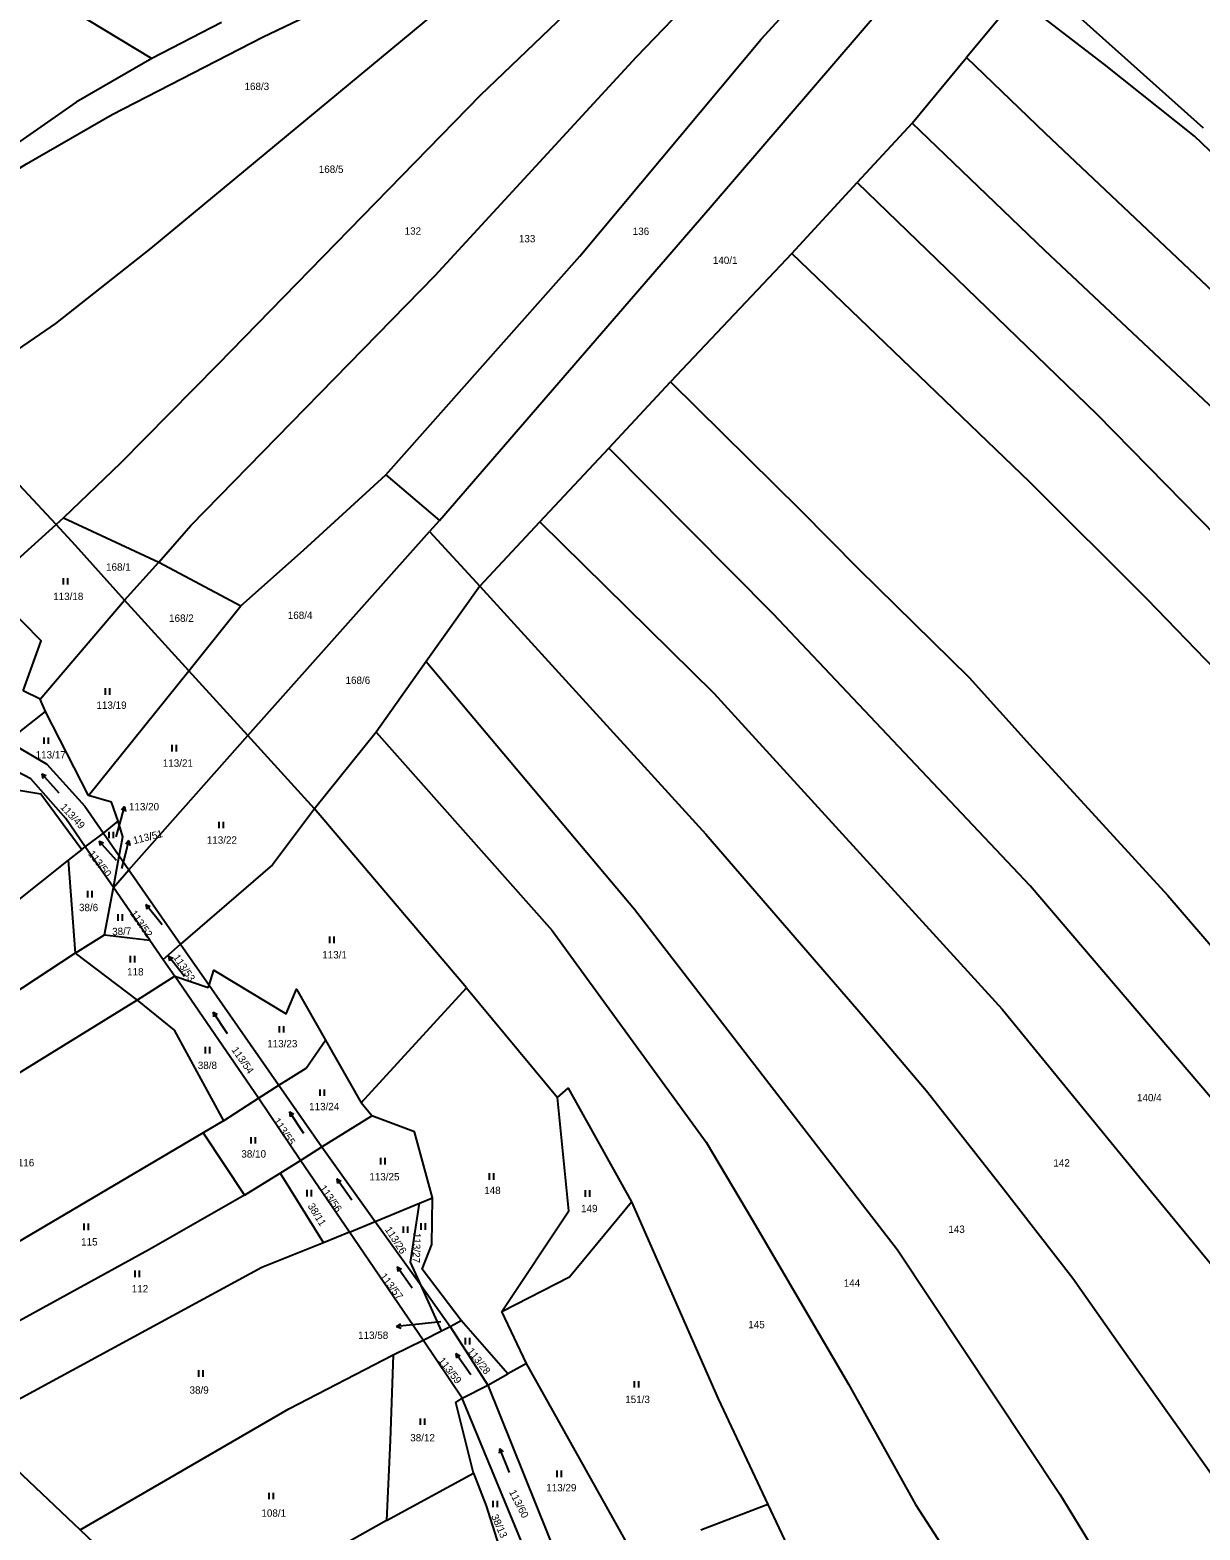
# Model space of a CAD drawing. Extents: x -7476540 to -746055, y -11317203 to -1129777.
# Drawn here: x -747546.5 to -747276.5, y -1131141.4 to -1130795.4 of the extents above; entities that cross this region are included whole.
import ezdxf

# ---------------------------------------------------------------- set-up
doc = ezdxf.new("R2010")
doc.units = 0
for name, color, linetype in [('Hranice parcel', 7, 'Continuous'), ('Parcelní čísla', 7, 'Continuous'), ('Pop  PČ popisy', 7, 'Continuous'), ('Značky kultur', 7, 'Continuous')]:
    doc.layers.add(name, color=color, linetype=linetype)

msp = doc.modelspace()

# ---------------------------------------------------------------- linework, layer by layer
at = {"layer": 'Hranice parcel'}
for p, q in [((-747318.79, -1130787.77), (-747330.4, -1130801.79)), ((-747275.7, -1130818.09), (-747307.66, -1130789.55)), ((-747502.34, -1130793.69), (-747518.4, -1130801.96)), ((-747342.93, -1130816.92), (-747330.4, -1130801.79)), ((-747342.93, -1130816.92), (-747355.62, -1130830.63)), ((-747370.72, -1130846.96), (-747355.62, -1130830.63)), ((-747370.72, -1130846.96), (-747398.68, -1130876.61)), ((-747412.97, -1130891.88), (-747398.68, -1130876.61)), ((-747540.5, -1130909.52), (-747566.95, -1130881.22)), ((-747428.85, -1130908.85), (-747412.97, -1130891.88)), ((-747464.43, -1130898), (-747452.04, -1130908.53)), ((-747538.78, -1130907.97), (-747540.5, -1130909.52)), ((-747538.78, -1130907.97), (-747516.82, -1130918.2)), ((-747556.37, -1130923.79), (-747540.5, -1130909.52)), ((-747496.26, -1130958.17), (-747454.36, -1130911.13)), ((-747452.04, -1130908.53), (-747454.36, -1130911.13)), ((-747454.36, -1130911.13), (-747442.73, -1130923.69)), ((-747442.73, -1130923.69), (-747428.85, -1130908.85)), ((-747524.7, -1130926.96), (-747516.82, -1130918.2)), ((-747516.82, -1130918.2), (-747497.88, -1130928.23)), ((-747442.73, -1130923.69), (-747455.08, -1130941.09)), ((-747544.17, -1130949.82), (-747524.7, -1130926.96)), ((-747509.89, -1130943.21), (-747524.7, -1130926.96)), ((-747509.89, -1130943.21), (-747497.88, -1130928.23)), ((-747455.08, -1130941.09), (-747466.65, -1130957.41)), ((-747533.01, -1130972.03), (-747509.89, -1130943.21)), ((-747496.26, -1130958.17), (-747509.89, -1130943.21)), ((-747544.17, -1130949.82), (-747548.12, -1130947.84)), ((-747542.97, -1130952.61), (-747544.17, -1130949.82)), ((-747551.66, -1130959.44), (-747542.97, -1130952.61)), ((-747533.01, -1130972.03), (-747542.97, -1130952.61)), ((-747523.68, -1130989.16), (-747496.26, -1130958.17)), ((-747480.85, -1130975.08), (-747496.26, -1130958.17)), ((-747466.65, -1130957.41), (-747480.85, -1130975.08)), ((-747445.77, -1131016.39), (-747480.85, -1130975.08)), ((-747533.76, -1130983.87), (-747529.57, -1130980.67)), ((-747529.57, -1130980.67), (-747526.17, -1130977.92)), ((-747529.57, -1130980.67), (-747525.94, -1130985.9)), ((-747534.58, -1130984.5), (-747537.72, -1130986.92)), ((-747534.58, -1130984.5), (-747533.76, -1130983.87)), ((-747527.29, -1130993.25), (-747533.76, -1130983.87)), ((-747537.72, -1130986.92), (-747536.11, -1131008.38)), ((-747527.29, -1130993.25), (-747525.94, -1130985.9)), ((-747525.94, -1130985.9), (-747523.68, -1130989.16)), ((-747527.29, -1130993.25), (-747523.68, -1130989.16)), ((-747523.68, -1130989.16), (-747511.77, -1131006.31)), ((-747529.3, -1131004.16), (-747527.29, -1130993.25)), ((-747518.9, -1131005.41), (-747527.29, -1130993.25)), ((-747536.11, -1131008.38), (-747529.3, -1131004.16)), ((-747529.3, -1131004.16), (-747518.9, -1131005.41)), ((-747536.11, -1131008.38), (-747521.83, -1131019.25)), ((-747518.9, -1131005.41), (-747515.79, -1131009.83)), ((-747515.79, -1131009.83), (-747511.77, -1131006.31)), ((-747511.77, -1131006.31), (-747505.21, -1131015.73)), ((-747515.79, -1131009.83), (-747513.08, -1131013.69)), ((-747513.08, -1131013.69), (-747521.83, -1131019.25)), ((-747493.76, -1131041.86), (-747513.08, -1131013.69)), ((-747505.21, -1131015.73), (-747489.11, -1131038.86)), ((-747470.12, -1131042.87), (-747445.77, -1131016.39)), ((-747445.77, -1131016.39), (-747424.82, -1131041.7)), ((-747478.31, -1131028.41), (-747470.12, -1131042.87)), ((-747493.76, -1131041.86), (-747489.11, -1131038.86)), ((-747489.11, -1131038.86), (-747479.21, -1131053.09)), ((-747501.87, -1131047.09), (-747493.76, -1131041.86)), ((-747484.08, -1131056.18), (-747493.76, -1131041.86)), ((-747467.67, -1131045.88), (-747470.12, -1131042.87)), ((-747479.21, -1131053.09), (-747467.67, -1131045.88)), ((-747501.87, -1131047.09), (-747506.57, -1131049.83)), ((-747506.57, -1131049.83), (-747497.04, -1131064.23)), ((-747484.08, -1131056.18), (-747479.21, -1131053.09)), ((-747479.21, -1131053.09), (-747466.89, -1131070.28)), ((-747488.78, -1131059.1), (-747484.08, -1131056.18)), ((-747472.77, -1131072.73), (-747484.08, -1131056.18)), ((-747497.04, -1131064.23), (-747488.78, -1131059.1)), ((-747488.78, -1131059.1), (-747478.83, -1131075.18)), ((-747466.89, -1131070.28), (-747456.65, -1131066.03)), ((-747456.65, -1131066.03), (-747453.62, -1131064.84)), ((-747472.77, -1131072.73), (-747466.89, -1131070.28)), ((-747466.89, -1131070.28), (-747456.29, -1131085.07)), ((-747472.77, -1131072.73), (-747478.83, -1131075.18)), ((-747455.83, -1131097.63), (-747472.77, -1131072.73)), ((-747456.29, -1131085.07), (-747449.55, -1131094.47)), ((-747451.56, -1131095.48), (-747456.29, -1131085.07)), ((-747431.95, -1131103.02), (-747437.65, -1131091.07)), ((-747451.56, -1131095.48), (-747449.55, -1131094.47)), ((-747449.55, -1131094.47), (-747447.06, -1131093.1)), ((-747449.55, -1131094.47), (-747440.84, -1131108.03)), ((-747436.27, -1131105.41), (-747447.06, -1131093.1)), ((-747462.74, -1131101.03), (-747455.83, -1131097.63)), ((-747455.83, -1131097.63), (-747451.56, -1131095.48)), ((-747446.81, -1131111.05), (-747455.83, -1131097.63)), ((-747440.84, -1131108.03), (-747436.27, -1131105.41)), ((-747431.95, -1131103.02), (-747436.27, -1131105.41)), ((-747408.38, -1131145.07), (-747431.95, -1131103.02)), ((-747446.81, -1131111.05), (-747440.84, -1131108.03)), ((-747440.84, -1131108.03), (-747424.22, -1131149.41)), ((-747430.18, -1131151.04), (-747446.81, -1131111.05)), ((-747551.23, -1131125.94), (-747534.94, -1131141.41)), ((-747464.26, -1131139.24), (-747444.14, -1131128.36)), ((-747376.22, -1131135.6), (-747391.74, -1131141.48)), ((-747518.15, -1131157.34), (-747534.94, -1131141.41))]:
    msp.add_line(p, q, dxfattribs=at)
for points in [[(-747650.43, -1130722.5), (-747624.13, -1130740.43), (-747611.24, -1130748.86), (-747568.75, -1130772.25), (-747551.99, -1130781.63), (-747518.4, -1130801.96)], [(-747592.89, -1130855.02), (-747567.07, -1130838.41), (-747547.35, -1130826.32), (-747527.53, -1130814.88), (-747492.89, -1130797.06), (-747472.69, -1130787.42), (-747441.69, -1130763.28), (-747417.46, -1130747.1), (-747393.87, -1130731.74)], [(-747566.95, -1130881.22), (-747540.53, -1130863.15), (-747518.65, -1130845.8), (-747451.1, -1130789.94), (-747421.34, -1130761.04), (-747390.31, -1130735.18)], [(-747375.64, -1130746.37), (-747442.58, -1130810.47), (-747503.21, -1130872.55), (-747525.65, -1130895.32), (-747538.78, -1130907.97)], [(-747516.82, -1130918.2), (-747509.43, -1130909.76), (-747453.02, -1130852.06), (-747406.54, -1130801.59), (-747362.47, -1130755.89)], [(-747464.43, -1130898), (-747419.65, -1130847.56), (-747377.79, -1130797.57), (-747349.46, -1130766.63)], [(-747452.04, -1130908.53), (-747389.53, -1130836.33), (-747337.16, -1130775.31)], [(-747003.4, -1131127.9), (-747038.28, -1131074.83), (-747088.46, -1131014.6), (-747116.47, -1130986.19), (-747124.97, -1130976.78), (-747183.56, -1130913.69), (-747214.38, -1130881.51), (-747246.16, -1130850.11), (-747277.78, -1130819.92), (-747298.57, -1130803.35), (-747318.79, -1130787.77)], [(-747518.4, -1130801.96), (-747535.86, -1130812.1), (-747550.62, -1130822.39), (-747567.45, -1130834.27)], [(-747330.4, -1130801.79), (-747312.28, -1130819.2), (-747236.13, -1130891.14), (-747221.8, -1130905.72), (-747180.22, -1130949.79), (-747146.85, -1130983.32), (-747109.33, -1131021.53), (-747071.58, -1131064.23), (-747049.91, -1131090.84), (-747024.34, -1131132)], [(-747047.94, -1131136.47), (-747061.48, -1131111.93), (-747077.88, -1131090.42), (-747092.86, -1131072.81), (-747117.23, -1131044.76), (-747147.18, -1131012.65), (-747177.53, -1130980.93), (-747224.92, -1130930.97), (-747274.38, -1130881.89), (-747312.29, -1130846.28), (-747342.93, -1130816.92)], [(-747355.62, -1130830.63), (-747300.42, -1130884), (-747284.49, -1130900.18), (-747229.45, -1130956.25), (-747195.44, -1130993.87), (-747158.72, -1131032.34), (-747137.46, -1131054.25), (-747087.92, -1131108.9), (-747067.99, -1131140.68)], [(-747092.53, -1131145.47), (-747103.44, -1131128.5), (-747151.55, -1131074.46), (-747210.89, -1131009.26), (-747228.17, -1130990.46), (-747257.09, -1130959.39), (-747288.71, -1130926.72), (-747315.79, -1130899.71), (-747370.72, -1130846.96)], [(-747398.68, -1130876.61), (-747368.77, -1130906.07), (-747355.31, -1130919.74), (-747329.82, -1130944.76), (-747315.8, -1130960.3), (-747283.94, -1130995.04), (-747236.86, -1131049.77), (-747149.88, -1131157.26)], [(-747177.21, -1131162.4), (-747204.46, -1131125.99), (-747254.48, -1131065.07), (-747271.84, -1131044.18), (-747315.73, -1130992.85), (-747375, -1130930.12), (-747412.97, -1130891.88)], [(-747497.88, -1130928.23), (-747483.39, -1130915.42), (-747464.43, -1130898)], [(-747524.7, -1130926.96), (-747536.03, -1130914.31), (-747540.5, -1130909.52)], [(-747428.85, -1130908.85), (-747388.68, -1130948.41), (-747322.17, -1131021.26), (-747287.68, -1131063.4), (-747257.57, -1131100.06), (-747233.11, -1131129.78), (-747216.94, -1131150.33), (-747204.99, -1131167.77)], [(-747548.12, -1130947.84), (-747543.96, -1130936.32), (-747556.37, -1130923.79)], [(-747442.73, -1130923.69), (-747390.58, -1130980.92), (-747354.26, -1131022.92), (-747339.61, -1131040.16), (-747322.4, -1131062.04), (-747305.83, -1131083.32), (-747294.44, -1131099.65), (-747274.04, -1131128.34), (-747243.06, -1131175.98)], [(-747455.08, -1130941.09), (-747407, -1130998.24), (-747346.3, -1131076.82), (-747308.86, -1131133.19), (-747276.68, -1131185.78)], [(-747551.66, -1130959.44), (-747542.61, -1130964.81), (-747533.86, -1130974.48), (-747529.57, -1130980.67)], [(-747466.65, -1130957.41), (-747426.05, -1131003.14), (-747390.52, -1131051.98), (-747379.77, -1131069.99), (-747357.62, -1131107.84), (-747342.16, -1131135.57), (-747326.23, -1131160.19), (-747318.42, -1131169.83), (-747304.55, -1131193.5)], [(-747533.76, -1130983.87), (-747538.28, -1130977.32), (-747546.35, -1130968.19), (-747556.12, -1130963.07)], [(-747562.63, -1130968.51), (-747544.05, -1130971.62), (-747534.58, -1130984.5)], [(-747526.17, -1130977.92), (-747527.69, -1130973.54), (-747533.01, -1130972.03)], [(-747480.85, -1130975.08), (-747490.53, -1130988), (-747511.77, -1131006.31)], [(-747525.94, -1130985.9), (-747525.13, -1130981.52), (-747526.17, -1130977.92)], [(-747537.72, -1130986.92), (-747564.39, -1131008.14), (-747611.03, -1131036.67), (-747627.11, -1131046.39)], [(-747536.11, -1131008.38), (-747587.97, -1131042.46), (-747616.38, -1131059.15)], [(-747513.08, -1131013.69), (-747505.41, -1131016.33), (-747505.21, -1131015.73)], [(-747505.21, -1131015.73), (-747504.08, -1131012.3), (-747487.41, -1131022.36), (-747485.06, -1131016.72), (-747478.31, -1131028.41)], [(-747521.83, -1131019.25), (-747565.86, -1131046.34), (-747605.42, -1131071.52)], [(-747521.83, -1131019.25), (-747513.23, -1131026.12), (-747501.87, -1131047.09)], [(-747489.11, -1131038.86), (-747482.82, -1131034.88), (-747478.31, -1131028.41)], [(-747424.82, -1131041.7), (-747422.32, -1131039.54), (-747407.71, -1131065.71)], [(-747437.65, -1131091.07), (-747422.19, -1131067.82), (-747424.82, -1131041.7)], [(-747453.62, -1131064.84), (-747457.76, -1131049.58), (-747467.67, -1131045.88)], [(-747506.57, -1131049.83), (-747567.11, -1131085.51), (-747578.6, -1131091.89), (-747583.1, -1131094.79)], [(-747497.04, -1131064.23), (-747519.1, -1131076.81), (-747571.91, -1131105.73)], [(-747456.29, -1131085.07), (-747458.74, -1131079.69), (-747456.65, -1131066.03)], [(-747447.06, -1131093.1), (-747456, -1131081.28), (-747453.76, -1131075.58), (-747453.62, -1131064.84)], [(-747437.65, -1131091.07), (-747422, -1131083.03), (-747407.71, -1131065.71)], [(-747407.71, -1131065.71), (-747387.68, -1131111.18), (-747376.22, -1131135.6)], [(-747478.83, -1131075.18), (-747493.05, -1131080.92), (-747560.11, -1131117.26)], [(-747534.94, -1131141.41), (-747486.76, -1131113.5), (-747462.74, -1131101.03)], [(-747462.74, -1131101.03), (-747463.44, -1131120.77), (-747464.26, -1131139.24)], [(-747444.14, -1131128.36), (-747448.25, -1131112.03), (-747446.81, -1131111.05)], [(-747444.14, -1131128.36), (-747441.29, -1131135.89), (-747437.88, -1131146.58), (-747434.26, -1131152.16)], [(-747376.22, -1131135.6), (-747368.67, -1131151.69), (-747335.3, -1131202.07)], [(-747464.26, -1131139.24), (-747483.41, -1131150.03), (-747508, -1131163.09)]]:
    msp.add_lwpolyline(points, dxfattribs=at)
at = {"layer": 'Pop  PČ popisy'}
for p, q in [((-747526.65, -1130981.51), (-747525.51, -1130977.47)), ((-747525.51, -1130977.47), (-747524.68, -1130974.58)), ((-747524.68, -1130974.58), (-747525.44, -1130975.41)), ((-747524.68, -1130974.58), (-747524.48, -1130975.69)), ((-747524.43, -1130985.33), (-747523.7, -1130982.42)), ((-747523.7, -1130982.42), (-747524.43, -1130983.27)), ((-747523.7, -1130982.42), (-747523.46, -1130983.51)), ((-747525.3, -1130988.86), (-747524.43, -1130985.33)), ((-747461.92, -1131094.51), (-747460.97, -1131093.91)), ((-747458.93, -1131094.2), (-747461.92, -1131094.51)), ((-747461.92, -1131094.51), (-747460.87, -1131094.91)), ((-747451.68, -1131093.42), (-747458.93, -1131094.2))]:
    msp.add_line(p, q, dxfattribs=at)
at = {"layer": 'Značky kultur'}
for p, q in [((-747538.76, -1130923.37), (-747538.76, -1130921.87)), ((-747537.76, -1130923.37), (-747537.76, -1130921.87)), ((-747529.1, -1130948.78), (-747529.1, -1130947.28)), ((-747528.1, -1130948.78), (-747528.1, -1130947.28)), ((-747543.24, -1130960.1), (-747543.24, -1130958.6)), ((-747542.24, -1130960.1), (-747542.24, -1130958.6)), ((-747513.74, -1130961.83), (-747513.74, -1130960.33)), ((-747512.74, -1130961.83), (-747512.74, -1130960.33)), ((-747539.8, -1130971.47), (-747543.81, -1130967.01)), ((-747543.81, -1130967.01), (-747543.53, -1130968.07)), ((-747543.81, -1130967.01), (-747542.79, -1130967.4)), ((-747528.22, -1130981.85), (-747528.22, -1130980.35)), ((-747527.22, -1130981.85), (-747527.22, -1130980.35)), ((-747502.9, -1130979.58), (-747502.9, -1130978.08)), ((-747501.9, -1130979.58), (-747501.9, -1130978.08)), ((-747526.57, -1130986.97), (-747530.58, -1130982.51)), ((-747530.58, -1130982.51), (-747530.3, -1130983.57)), ((-747530.58, -1130982.51), (-747529.56, -1130982.9)), ((-747533.17, -1130995.51), (-747533.17, -1130994.01)), ((-747532.17, -1130995.51), (-747532.17, -1130994.01)), ((-747516, -1131001.81), (-747519.77, -1130997.15)), ((-747519.77, -1130997.15), (-747519.55, -1130998.23)), ((-747519.77, -1130997.15), (-747518.77, -1130997.59)), ((-747526.2, -1131000.89), (-747526.2, -1130999.39)), ((-747525.2, -1131000.89), (-747525.2, -1130999.39)), ((-747477.3, -1131006.05), (-747477.3, -1131004.55)), ((-747476.3, -1131006.05), (-747476.3, -1131004.55)), ((-747523.33, -1131010.52), (-747523.33, -1131009.02)), ((-747522.33, -1131010.52), (-747522.33, -1131009.02)), ((-747510.87, -1131013.79), (-747514.56, -1131009.07)), ((-747514.56, -1131009.07), (-747514.35, -1131010.15)), ((-747514.56, -1131009.07), (-747513.56, -1131009.53)), ((-747500.93, -1131026.98), (-747504.28, -1131022)), ((-747504.28, -1131022), (-747504.15, -1131023.09)), ((-747504.28, -1131022), (-747503.32, -1131022.53)), ((-747488.94, -1131026.68), (-747488.94, -1131025.18)), ((-747487.94, -1131026.68), (-747487.94, -1131025.18)), ((-747506.04, -1131031.49), (-747506.04, -1131029.99)), ((-747505.04, -1131031.49), (-747505.04, -1131029.99)), ((-747479.54, -1131041.31), (-747479.54, -1131039.81)), ((-747478.54, -1131041.31), (-747478.54, -1131039.81)), ((-747483.3, -1131049.99), (-747486.65, -1131045.01)), ((-747486.65, -1131045.01), (-747486.52, -1131046.1)), ((-747486.65, -1131045.01), (-747485.69, -1131045.54)), ((-747495.49, -1131052.29), (-747495.49, -1131050.79)), ((-747494.49, -1131052.29), (-747494.49, -1131050.79)), ((-747465.54, -1131057.13), (-747465.54, -1131055.63)), ((-747464.54, -1131057.13), (-747464.54, -1131055.63)), ((-747472.25, -1131065.37), (-747475.69, -1131060.45)), ((-747475.69, -1131060.45), (-747475.54, -1131061.54)), ((-747475.69, -1131060.45), (-747474.72, -1131060.97)), ((-747440.46, -1131060.63), (-747440.46, -1131059.13)), ((-747439.46, -1131060.63), (-747439.46, -1131059.13)), ((-747482.54, -1131064.49), (-747482.54, -1131062.99)), ((-747481.54, -1131064.49), (-747481.54, -1131062.99)), ((-747418.34, -1131064.58), (-747418.34, -1131063.08)), ((-747417.34, -1131064.58), (-747417.34, -1131063.08)), ((-747533.99, -1131072.27), (-747533.99, -1131070.77)), ((-747532.99, -1131072.27), (-747532.99, -1131070.77)), ((-747456.23, -1131072.2), (-747456.23, -1131070.7)), ((-747455.23, -1131072.2), (-747455.23, -1131070.7)), ((-747460.34, -1131072.91), (-747460.34, -1131071.41)), ((-747459.34, -1131072.91), (-747459.34, -1131071.41)), ((-747458.35, -1131085.65), (-747461.79, -1131080.73)), ((-747461.79, -1131080.73), (-747461.64, -1131081.82)), ((-747461.79, -1131080.73), (-747460.82, -1131081.25)), ((-747522.27, -1131083.09), (-747522.27, -1131081.59)), ((-747521.27, -1131083.09), (-747521.27, -1131081.59)), ((-747446.04, -1131098.65), (-747446.04, -1131097.15)), ((-747445.04, -1131098.65), (-747445.04, -1131097.15)), ((-747444.81, -1131105.63), (-747448.25, -1131100.71)), ((-747448.25, -1131100.71), (-747448.1, -1131101.8)), ((-747448.25, -1131100.71), (-747447.28, -1131101.23)), ((-747507.6, -1131106.09), (-747507.6, -1131104.59)), ((-747506.6, -1131106.09), (-747506.6, -1131104.59)), ((-747407.04, -1131108.61), (-747407.04, -1131107.11)), ((-747406.04, -1131108.61), (-747406.04, -1131107.11)), ((-747456.41, -1131117.21), (-747456.41, -1131115.71)), ((-747455.41, -1131117.21), (-747455.41, -1131115.71)), ((-747438.13, -1131122.64), (-747438.23, -1131123.73)), ((-747435.89, -1131128.2), (-747438.13, -1131122.64)), ((-747438.13, -1131122.64), (-747437.3, -1131123.36)), ((-747424.88, -1131129.23), (-747424.88, -1131127.73)), ((-747423.88, -1131129.23), (-747423.88, -1131127.73)), ((-747491.32, -1131134.35), (-747491.32, -1131132.85)), ((-747490.32, -1131134.35), (-747490.32, -1131132.85)), ((-747439.63, -1131136.2), (-747439.63, -1131134.7)), ((-747438.63, -1131136.2), (-747438.63, -1131134.7))]:
    msp.add_line(p, q, dxfattribs=at)

# ---------------------------------------------------------------- texts
at = {"layer": 'Parcelní čísla'}
for s, p in [('168/3', (-747497.02, -1130809.28)), ('168/5', (-747479.88, -1130828.38)), ('132', (-747460.07, -1130842.63)), ('136', (-747407.43, -1130842.7)), ('133', (-747433.7, -1130844.4)), ('140/1', (-747388.94, -1130849.39)), ('168/1', (-747528.97, -1130920.14)), ('113/18', (-747541.17, -1130926.92)), ('168/2', (-747514.43, -1130931.95)), ('168/4', (-747487.03, -1130931.28)), ('168/6', (-747473.71, -1130946.27)), ('113/19', (-747531.19, -1130952.02)), ('113/17', (-747545.22, -1130963.46)), ('113/21', (-747515.88, -1130965.38)), ('113/20', (-747523.69, -1130975.43)), ('113/22', (-747505.72, -1130983.13)), ('38/6', (-747535.22, -1130998.69)), ('113/1', (-747479.08, -1131009.6)), ('118', (-747524.11, -1131013.52)), ('113/23', (-747491.78, -1131030.1)), ('38/8', (-747507.8, -1131035.1)), ('113/24', (-747482.11, -1131044.61)), ('140/4', (-747291.06, -1131042.55)), ('116', (-747549.33, -1131057.56)), ('38/10', (-747497.75, -1131055.53)), ('142', (-747310.35, -1131057.61)), ('113/25', (-747468.21, -1131060.8)), ('148', (-747441.7, -1131063.95)), ('149', (-747419.35, -1131068.13)), ('115', (-747534.73, -1131075.82)), ('143', (-747334.59, -1131072.91)), ('144', (-747358.73, -1131085.33)), ('112', (-747523.04, -1131086.64)), ('145', (-747380.76, -1131094.9)), ('113/58', (-747470.81, -1131097.37)), ('38/9', (-747509.71, -1131110.01)), ('151/3', (-747409.16, -1131112.16)), ('38/12', (-747458.77, -1131121)), ('113/29', (-747427.38, -1131132.53)), ('108/1', (-747493.12, -1131138.39))]:
    msp.add_text(s, height=1.7, dxfattribs=at).set_placement(p)
for s, rotation, p in [('113/49', 313, (-747539.66, -1130974.8)), ('113/51', 14, (-747522.5, -1130983.24)), ('113/50', 308, (-747533.21, -1130985.52)), ('113/52', 305, (-747523.52, -1130999.23)), ('38/7', 2, (-747527.53, -1131004.26)), ('113/53', 304, (-747513.58, -1131009.35)), ('113/54', 305, (-747500.1, -1131030.7)), ('113/55', 304, (-747490.46, -1131047.1)), ('113/56', 305, (-747479.79, -1131062.6)), ('38/11', 302, (-747482.52, -1131066.7)), ('113/26', 303, (-747464.71, -1131072.12)), ('113/27', 268, (-747458.02, -1131072.87)), ('113/57', 307, (-747465.84, -1131082.95)), ('113/59', 308, (-747452.4, -1131102.42)), ('113/28', 308, (-747445.72, -1131100.24)), ('113/60', 297, (-747436.02, -1131132.68)), ('38/13', 294, (-747440.15, -1131138.28))]:
    msp.add_text(s, height=1.7, rotation=rotation, dxfattribs=at).set_placement(p)

doc.saveas('drawing.dxf')
